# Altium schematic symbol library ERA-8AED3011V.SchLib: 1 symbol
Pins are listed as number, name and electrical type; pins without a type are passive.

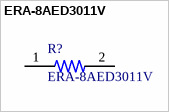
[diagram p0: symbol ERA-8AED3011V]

## ERA-8AED3011V
designator R?
Res Thin Film 1206 3.01K Ohm 0.5% 1/4W Â±25ppm/Â°C Molded SMD SMD Punched Carrier T/R; MF: Panasonic
footprint RESC3216X70
pins: 1, 2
